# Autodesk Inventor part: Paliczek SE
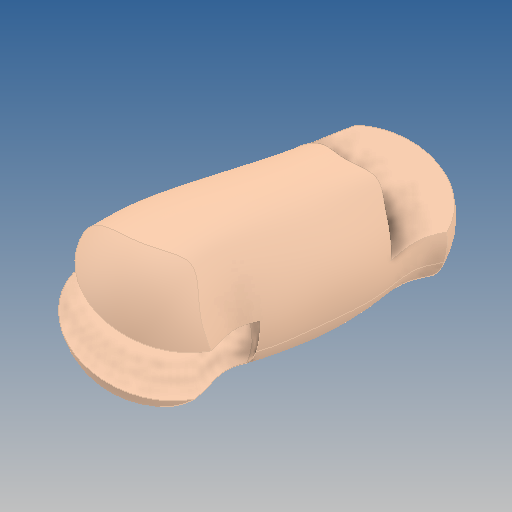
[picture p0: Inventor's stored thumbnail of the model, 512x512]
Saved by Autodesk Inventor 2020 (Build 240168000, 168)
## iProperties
Created: 2019-10
Part Number: Paliczek SE
Material: GFRP
Document SubType Name: Modeling
Designer: yello
Density: 1.75 g/cm^3
Appearance: Default
Author: yello
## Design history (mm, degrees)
feature "Paliczek SE"
body "Solid1"
